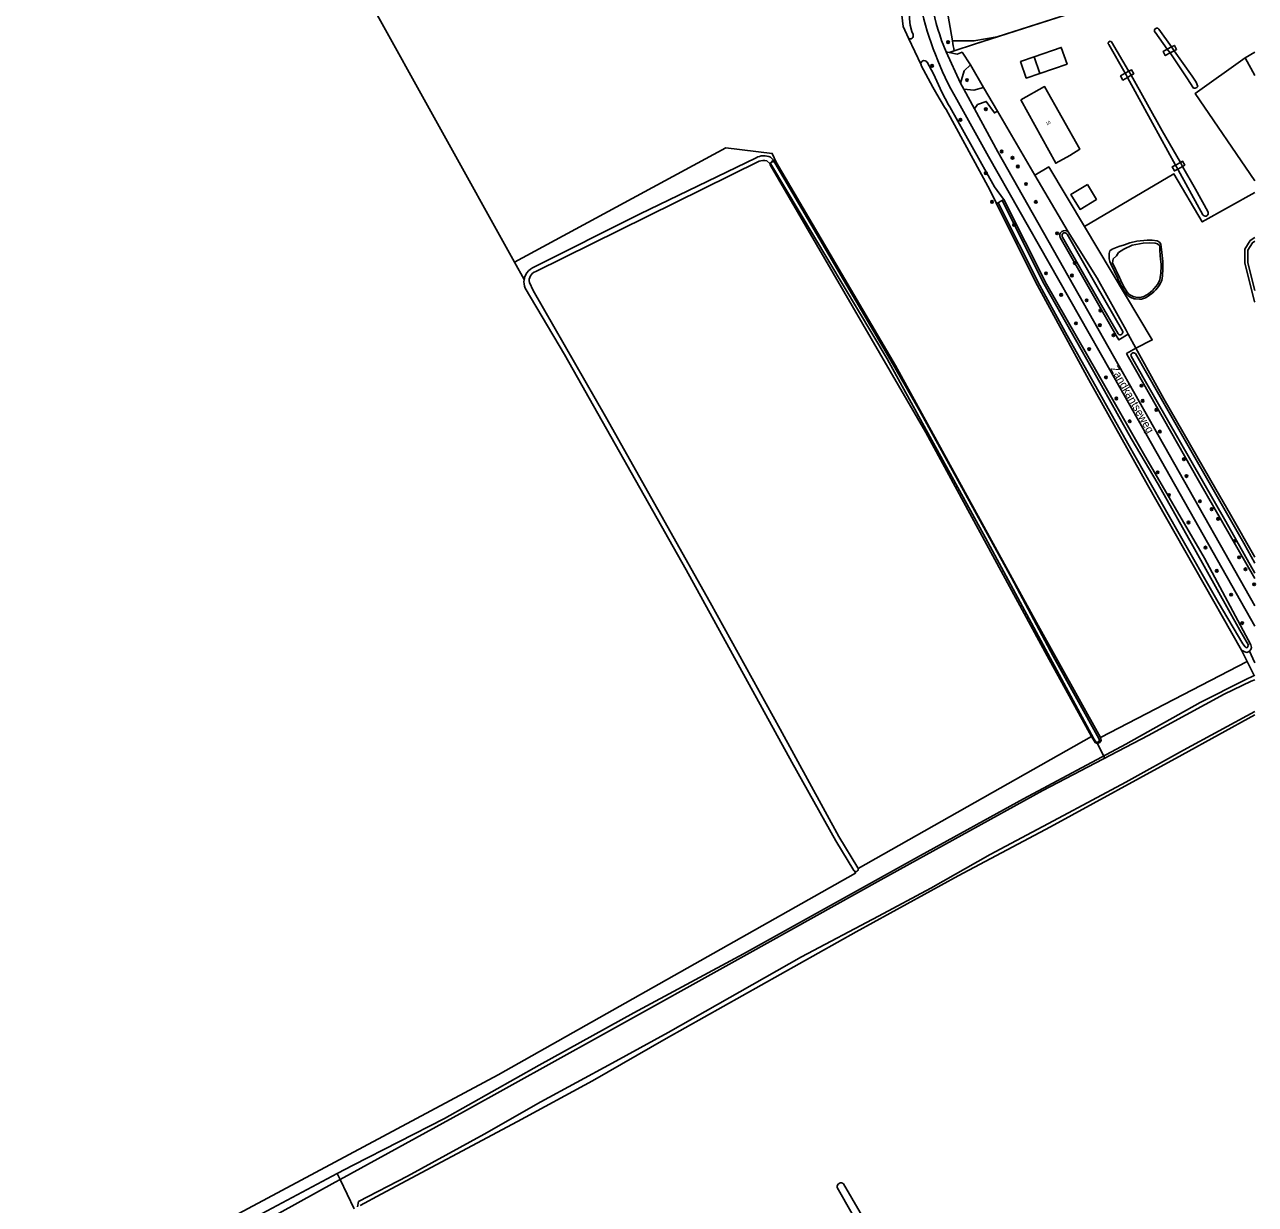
# Model space of a CAD drawing. Extents: x 137000 to 140001, y 403500 to 406000.
# Drawn here: x 139615.6 to 140000.1, y 405109.4 to 405478.2 of the extents above; entities that cross this region are included whole.
import ezdxf

# ---------------------------------------------------------------- set-up
doc = ezdxf.new("R2010")
doc.units = 0
for name, color, linetype in [('gg-afsc-draadraster', 7, 'Continuous'), ('gg-afsc-erfafscheiding', 7, 'Continuous'), ('gg-afsc-hekwerk', 7, 'Continuous'), ('gg-afsc-lijn draadraster', 7, 'Continuous'), ('gg-anno-huisnummerreeks BGT', 7, 'Continuous'), ('gg-anno-openbare ruimte label', 7, 'Continuous'), ('gg-bbg-bijgebouw', 7, 'Continuous'), ('gg-bbg-hoofdgebouw', 7, 'Continuous'), ('gg-bbg-luifel en loopbrug', 7, 'Continuous'), ('gg-knt-bronhoudergrens', 7, 'Continuous'), ('gg-knt-verharding', 7, 'Continuous'), ('gg-knt-verharding nz', 7, 'Continuous'), ('gg-kntw-bovenkant insteek waterloop', 7, 'Continuous'), ('gg-kntw-waterlijn', 7, 'Continuous'), ('gg-kwrk-duiker nz buis', 7, 'Continuous'), ('gg-kwrk-kunstwerk niveau 01', 7, 'Continuous'), ('gt-grn-groengrens', 7, 'Continuous'), ('gt-grn-vlakafsluiter', 7, 'Continuous'), ('gt-symb-boom', 7, 'Continuous')]:
    doc.layers.add(name, color=color, linetype=linetype)

# ---------------------------------------------------------------- blocks, each defined once
blk = doc.blocks.new('gt0-BOOM')
at = {"layer": 'gt-symb-boom'}
for radius in [0.4, 0.2]:
    blk.add_circle((0, 0), radius, dxfattribs=at)

msp = doc.modelspace()

# ---------------------------------------------------------------- linework, layer by layer
at = {"layer": 'gg-afsc-draadraster'}
msp.add_line((139996.89, 405467.83), (140000, 405469.63), dxfattribs=at)
msp.add_lwpolyline([(139996.89, 405467.83), (139981.26, 405456.64), (140000, 405429.35)], dxfattribs=at)
at = {"layer": 'gg-afsc-erfafscheiding'}
msp.add_line((139905.98, 405470.03), (139904.45, 405469.53), dxfattribs=at)
msp.add_lwpolyline([(139919.46, 405474.37), (139912.34, 405472.08), (139905.98, 405470.03)], dxfattribs=at)
at = {"layer": 'gg-afsc-hekwerk'}
msp.add_lwpolyline([(139949.33, 405509.28), (139949.11, 405507.9), (139952.74, 405507.73), (139952.66, 405502.48), (139962.18, 405502.59), (139962.54, 405493.26), (139961.71, 405490.23), (139960.66, 405488.19), (139958.88, 405487.07), (139912.34, 405472.08)], dxfattribs=at)
at = {"layer": 'gg-afsc-lijn draadraster'}
msp.add_line((139996.89, 405467.83), (140000, 405469.63), dxfattribs=at)
at = {"layer": 'gg-bbg-bijgebouw'}
msp.add_line((139932.81, 405462.96), (139931.02, 405468.15), dxfattribs=at)
msp.add_lwpolyline([(139932.81, 405462.96), (139941.28, 405465.86), (139939.48, 405471.07), (139931.02, 405468.15)], dxfattribs=at)
at = {"layer": 'gg-bbg-hoofdgebouw'}
msp.add_lwpolyline([(139926.82, 405454.72), (139937.73, 405434.9), (139942.11, 405437.31), (139945.26, 405439.25), (139934.27, 405458.82), (139926.82, 405454.72)], dxfattribs=at)
at = {"layer": 'gg-bbg-luifel en loopbrug'}
for points in [[(139932.81, 405462.96), (139928.56, 405461.49), (139926.77, 405466.68), (139931.02, 405468.15)], [(139947.62, 405428.26), (139942.5, 405425.14), (139945.36, 405420.45), (139950.48, 405423.56), (139947.62, 405428.26)]]:
    msp.add_lwpolyline(points, dxfattribs=at)
at = {"layer": 'gg-knt-bronhoudergrens'}
for p, q in [((139903.77, 405483.23), (139905.51, 405473.1)), ((139996.89, 405467.83), (140000, 405462.35))]:
    msp.add_line(p, q, dxfattribs=at)
for points in [[(139919.46, 405474.37), (139958.88, 405487.07), (139960.66, 405488.19), (139960.93, 405502.58), (139952.66, 405502.48), (139952.74, 405507.73), (139949.11, 405507.9), (139949.33, 405509.28)], [(139905.51, 405473.1), (139912.21, 405473.1), (139919.46, 405474.37)], [(139946.69, 405415.12), (139974.67, 405431.55), (139983.51, 405416.52), (140000, 405425.77)]]:
    msp.add_lwpolyline(points, dxfattribs=at)
msp.add_arc((139512.03, 405411.17), 398.32, 8.4971, 8.9449, dxfattribs=at)
at = {"layer": 'gg-knt-verharding'}
for p, q in [((139903.49, 405469.73), (139904.45, 405469.53)), ((139908.01, 405459.91), (139909, 405458.08)), ((139909, 405458.08), (139912.18, 405457.76)), ((139915.23, 405458.54), (139912.18, 405457.76)), ((139912.35, 405451.91), (139913.35, 405453.21))]:
    msp.add_line(p, q, dxfattribs=at)
for points in [[(139904.45, 405469.53), (139906.93, 405469.02), (139908.51, 405469.56), (139911.1, 405465.59)], [(139908.01, 405459.91), (139909.19, 405463.76), (139911.1, 405465.59)], [(139906.85, 405454.77), (139916.7, 405436.99), (139954.63, 405370.27), (140000, 405290.13)], [(139913.35, 405453.21), (139916.04, 405454.2), (139918.57, 405450.59), (139919.55, 405451.15)], [(139912.35, 405451.91), (139919.66, 405438.45), (140000, 405296.57)]]:
    msp.add_lwpolyline(points, dxfattribs=at)
for centre, radius, start, end in [((139967.89, 405497.06), 69.97, 178.4624, 202.9964), ((139996.18, 405506.02), 102.99, 192.503, 209.8436)]:
    msp.add_arc(centre, radius, start, end, dxfattribs=at)
at = {"layer": 'gg-knt-verharding nz'}
for p, q in [((139908.01, 405459.91), (139903.49, 405469.73)), ((139912.35, 405451.91), (139909, 405458.08))]:
    msp.add_line(p, q, dxfattribs=at)
at = {"layer": 'gg-kntw-bovenkant insteek waterloop'}
for p, q in [((139968.76, 405475.81), (139972.61, 405470.52)), ((139973.9, 405471.23), (139969.98, 405476.8)), ((139954.29, 405471.98), (139959.49, 405463.01)), ((139972.61, 405470.52), (139973.45, 405469.37)), ((139974.72, 405470.06), (139973.9, 405471.23)), ((139961.28, 405462.36), (139960.57, 405463.64)), ((139775.32, 405400.99), (139845.06, 405435.51)), ((139847.51, 405435.62), (139848.39, 405434.79)), ((139849.56, 405435.83), (139848.63, 405436.76)), ((139977.38, 405433.9), (139976.68, 405435.13)), ((139975.2, 405434.31), (139975.88, 405433.07)), ((139998.48, 405410.74), (140000, 405411.67)), ((139962.67, 405392.45), (139963.88, 405392.36)), ((139992.32, 405325.07), (140000, 405311.71)), ((139999.69, 405274.73), (140000, 405274.88))]:
    msp.add_line(p, q, dxfattribs=at)
for points in [[(139892.17, 405539.02), (139891.48, 405534.95), (139890.95, 405527.36), (139890.42, 405519.81), (139889.87, 405499.46), (139889.66, 405481.14), (139890.07, 405477.6), (139891.71, 405473.94)], [(139893.17, 405475.09), (139892.78, 405476.06), (139892.23, 405477.99), (139892.06, 405479.99), (139892.16, 405506.35), (139893.15, 405526.22), (139894.29, 405537.64), (139894.17, 405538.4), (139893.52, 405538.97), (139892.57, 405539.28), (139892.17, 405539.02)], [(139960.57, 405463.64), (139960.48, 405463.79), (139955.19, 405472.86)], [(139973.45, 405469.37), (139974.09, 405468.49), (139978.71, 405461.55), (139980.82, 405458.37)], [(139980.82, 405458.37), (139981.29, 405458.32), (139981.86, 405458.54), (139982.11, 405458.9), (139981.63, 405460.19), (139980.34, 405462.08), (139974.72, 405470.06)], [(139895.74, 405465.45), (139899.38, 405458.66), (139900.63, 405456.42), (139903.04, 405452.4), (139903.48, 405451.67), (139917.2, 405426.61), (139919.11, 405422.49), (139919.26, 405422.18)], [(139897.53, 405466.46), (139899.51, 405462.81), (139902.14, 405457.06), (139904.27, 405453.14), (139904.63, 405452.49), (139918.61, 405427.5), (139921.48, 405423.6), (139921.5, 405423.55)], [(139959.49, 405463.01), (139959.78, 405462.49), (139960.2, 405461.73)], [(139960.2, 405461.73), (139967.97, 405447.42), (139975.2, 405434.31)], [(139976.68, 405435.13), (139971.04, 405445.05), (139961.28, 405462.36)], [(139844.11, 405436.61), (139807.75, 405419.01), (139774.33, 405402.14)], [(139848.39, 405434.79), (139848.58, 405434.41), (139897.17, 405350.75), (139935.02, 405280.88), (139948.96, 405255.72)], [(139849.56, 405435.83), (139849.72, 405435.66), (139850.03, 405435.52), (139850.39, 405435.17)], [(139951.69, 405255.35), (139931.74, 405291.33), (139887.71, 405371.68), (139850.39, 405435.17)], [(139975.88, 405433.07), (139976.64, 405431.7), (139983.72, 405418.76), (139983.79, 405418.63)], [(139985.24, 405419.77), (139981.44, 405426.75), (139977.38, 405433.9)], [(139921.5, 405423.55), (139934.89, 405397.1), (139950.61, 405369.68), (139965.19, 405344.1), (139984.19, 405311.46), (139998.73, 405284.33), (139998.88, 405283.49), (139998.71, 405282.85), (139998.14, 405282.3), (139997.46, 405281.95), (139996.82, 405282.12), (139995.81, 405282.68)], [(139995.81, 405282.68), (139966.38, 405334.34), (139948.09, 405367.2), (139932.1, 405396.62), (139919.26, 405422.18)], [(139939.15, 405411.63), (139956.63, 405381.03), (139957.48, 405379.66), (139960.33, 405381.46)], [(139960.33, 405381.46), (139959.7, 405382.7), (139950.66, 405398.94), (139941.65, 405413.43)], [(139954.64, 405407.46), (139955.41, 405408.06), (139957.44, 405408.83), (139959.23, 405409.38), (139960.86, 405409.98), (139963.11, 405410.53), (139966.35, 405410.84), (139967.84, 405410.84), (139969.42, 405410.63), (139970.15, 405410.25), (139970.58, 405409.62), (139970.84, 405407.9)], [(139971.19, 405404.12), (139970.99, 405406.01), (139970.84, 405407.9)], [(139998.48, 405410.74), (139996.81, 405407.99), (139996.8, 405403.61), (139999.84, 405391.67), (140000, 405391.43)], [(139954.63, 405404.21), (139954.95, 405403.44), (139957.14, 405398.88)], [(139875.89, 405214.66), (139869.99, 405224.46), (139851.67, 405257.93), (139829.83, 405297.55), (139797.11, 405355.71), (139774.48, 405395.05), (139773.33, 405397.55)], [(139772.03, 405395.84), (139784.29, 405375.09), (139822.26, 405307.74), (139855.33, 405247.62), (139869.07, 405223.05), (139874.67, 405213.82)], [(139962.74, 405377.03), (139959.89, 405375.36), (139960.48, 405374.27), (139982.38, 405335.68), (140000, 405305.06)], [(139962.74, 405377.03), (139971.48, 405361.24), (139987.73, 405333.05), (139992.32, 405325.07)], [(139713.25, 405119.05), (139718.23, 405121.7), (139746.77, 405136.3), (139776.4, 405152.99), (139805.97, 405169.29), (139840.17, 405187.79), (139895.48, 405218.53), (139927.63, 405236.19), (139959.63, 405253.27), (139982.83, 405266.29), (139996.73, 405273.34), (139999.69, 405274.73)], [(139720.46, 405109.08), (139726.96, 405112.65), (139769.64, 405135.32), (139793.02, 405148.07), (139816.05, 405161.34), (139875.4, 405194.59), (139907.26, 405212.09), (139936.13, 405227.47), (139977.28, 405249.99), (140000, 405262.5)], [(139951.69, 405255.35), (139951.89, 405254.46), (139951.52, 405253.82), (139950.69, 405253.47), (139950.02, 405253.81), (139948.96, 405255.72)], [(139321.86, 405130.61), (139321.9, 405130.59), (139342.21, 405123.62), (139362.87, 405116.99), (139403.41, 405105.03), (139431.04, 405095.93), (139470.53, 405084.33), (139486.29, 405079.55), (139504.58, 405076.23), (139518.93, 405074.14), (139535.06, 405072.93), (139561.32, 405073.71), (139581.35, 405074.51), (139611.69, 405076.38), (139623.03, 405077.25), (139630.19, 405078.39), (139641.27, 405080.96), (139645.19, 405082.1), (139657.99, 405088.41), (139689.81, 405106.6), (139713.25, 405119.05)], [(139871.47, 405115.85), (139888.5, 405086.48), (139900.59, 405070.28), (139922.75, 405039.87), (139934.17, 405022.42), (139951.05, 404993.55), (139978.73, 404945.63), (139994.45, 404919.61), (140000, 404910)], [(139869.45, 405114.72), (139887, 405083.98), (139904.45, 405060.72), (139920.22, 405038.4), (139936.44, 405012.98), (139970.64, 404954.01), (139989.67, 404922.16)]]:
    msp.add_lwpolyline(points, dxfattribs=at)
for centre, radius, start, end in [((139969.35, 405476.33), 0.785, 36.6568, 221.1306), ((139892.31, 405474.69), 0.953, 231.5488, 25.1922), ((139954.77, 405472.38), 0.632, 49.3856, 220.1645), ((139896.63, 405465.96), 1.03, 29.231, 200.8802), ((139896.54, 405465.92), 0.936, 200.5815, 210.283), ((139846.53, 405432.04), 5.17, 66.0443, 117.9353), ((139846.53, 405430.14), 5.57, 79.8848, 105.2651), ((139984.5, 405419.22), 0.921, 220.2299, 36.5356), ((139940.58, 405412.28), 1.57, 47.0531, 204.4377), ((139960.42, 405405.82), 6.01, 164.1692, 195.5133), ((139945.21, 405402.62), 26.02, 350.2457, 3.3023), ((139776.74, 405397.81), 5.11, 155.6015, 172.3704), ((139775.98, 405398.22), 4.25, 112.8736, 156.4334), ((139776.12, 405398.23), 2.88, 106.2258, 193.641), ((139776.73, 405397.81), 5.11, 172.415, 202.7913), ((139980.76, 405408.44), 25.48, 202.0301, 213.9325), ((139960.87, 405402.56), 10.89, 300.0032, 336.4588), ((139963.31, 405397.08), 4.67, 217.7841, 262.1661), ((139963.88, 405396.59), 4.23, 269.8733, 305.1442), ((139875.32, 405214.21), 0.758, 211.1163, 236.446), ((139875.31, 405214.2), 0.747, 236.6567, 17.5718), ((139875.32, 405214.21), 0.73, 17.2651, 38.5294), ((139870.65, 405114.95), 1.22, 47.5261, 190.8625)]:
    msp.add_arc(centre, radius, start, end, dxfattribs=at)
at = {"layer": 'gg-kntw-waterlijn'}
for p, q in [((139921.5, 405423.55), (139921.05, 405423.28)), ((139919.81, 405422.52), (139919.26, 405422.18)), ((139962.75, 405393.04), (139963.88, 405392.96))]:
    msp.add_line(p, q, dxfattribs=at)
for points in [[(139849.56, 405435.83), (139849.07, 405435.39), (139848.39, 405434.79)], [(139885.07, 405373.76), (139915.79, 405317.82), (139949.61, 405254.95), (139950.32, 405254.02), (139950.8, 405253.85), (139951.4, 405254.38), (139951.26, 405255.11), (139936.98, 405280.8), (139923.93, 405305.27), (139895.2, 405357.56), (139885.54, 405374.45), (139849.96, 405435.03), (139849.65, 405435.33), (139849.19, 405435.32), (139848.64, 405434.8), (139885.07, 405373.76)], [(139919.81, 405422.52), (139932.78, 405396.66), (139940.84, 405381.99), (139960.27, 405347.3), (139975.9, 405319.73), (139988.48, 405297.65), (139996.17, 405284.68), (139996.91, 405283.73), (139997.27, 405283.43), (139997.6, 405283.56), (139997.9, 405283.98), (139997.92, 405284.26), (139995.29, 405288.91), (139981.06, 405314.4), (139969.74, 405334.52), (139961.28, 405348.83), (139950.57, 405368.02), (139934.5, 405396.37), (139934.18, 405397.08), (139921.05, 405423.28)], [(139939.85, 405411.82), (139951.34, 405391.81), (139957.26, 405381.51)], [(139941.27, 405412.71), (139950.27, 405397.01), (139958.66, 405382.32)], [(139957.68, 405399.12), (139955.49, 405403.7), (139955.58, 405404.36), (139955.74, 405404.96), (139956.69, 405405.9), (139957.36, 405406.93), (139958.98, 405408), (139961.63, 405409.3), (139965.07, 405409.86), (139967.16, 405409.98), (139968.79, 405409.86), (139969.58, 405409.66), (139970.24, 405409.03)], [(139970.6, 405404.05), (139970.4, 405405.95), (139970.24, 405407.86)], [(140000, 405395.1), (139997.8, 405403.74), (139997.81, 405407.71), (139999.21, 405410.01), (140000, 405410.5)], [(139961.27, 405374.54), (139965.37, 405367.41), (139990.87, 405322.87), (140000, 405306.7)], [(139962.62, 405375.4), (139969.95, 405362.56), (139996.48, 405316.16), (140000, 405309.86)], [(139714.15, 405117.2), (139752.77, 405138.38), (139795.51, 405162.12), (139841.2, 405187.59), (139883.15, 405210.91), (139933.76, 405238.79), (139966.62, 405256.02), (139990.4, 405268.95), (139998.81, 405272.98), (140000, 405273.41)], [(139719.64, 405108.64), (139719.88, 405110.33), (139735.27, 405118.26), (139759.13, 405131.34), (139776.93, 405141.49), (139799.18, 405153.57), (139816.65, 405163.15), (139858.28, 405186.77), (139882.37, 405199.48), (139898.68, 405208.32), (139917.24, 405218.84), (139938.62, 405230.16), (139959.66, 405241.4), (139977.62, 405251.4), (140000, 405263.48)], [(139321.3, 405128.59), (139353.84, 405117.82), (139377.3, 405110.72), (139422.14, 405096.54), (139442.29, 405090.31), (139466.56, 405083.22), (139488.65, 405076.93), (139508.21, 405073.15), (139527.27, 405070.94), (139553.54, 405070.96), (139597.72, 405073.56), (139633.61, 405076.45), (139640.23, 405077.65), (139643.83, 405078.55), (139646.18, 405079.24), (139648.76, 405080.32), (139672.72, 405094.25), (139712.6, 405116.35), (139714.15, 405117.2)]]:
    msp.add_lwpolyline(points, dxfattribs=at)
for centre, radius, start, end in [((139940.55, 405412.28), 0.84, 31.0045, 213.3463), ((139964.71, 405408.4), 5.56, 354.4253, 6.55), ((139946.03, 405402.51), 24.62, 350.5161, 3.5969), ((139980.49, 405408.29), 24.58, 201.8921, 213.8909), ((139960.87, 405402.56), 10.3, 299.8497, 336.4564), ((139963.31, 405397.08), 4.08, 217.7787, 262.1638), ((139963.89, 405396.58), 3.62, 269.8254, 305.6287), ((139957.88, 405382.06), 0.827, 222.2115, 17.7352), ((139962.07, 405374.77), 0.833, 48.8607, 196.2136)]:
    msp.add_arc(centre, radius, start, end, dxfattribs=at)
at = {"layer": 'gg-kwrk-duiker nz buis'}
for p, q in [((139998.17, 405282.59), (140000, 405278.69)), ((139950.68, 405253.66), (139952.94, 405248.98))]:
    msp.add_line(p, q, dxfattribs=at)
at = {"layer": 'gg-kwrk-kunstwerk niveau 01'}
for p, q in [((139973.9, 405471.23), (139972.61, 405470.52)), ((139974.72, 405470.06), (139973.45, 405469.37)), ((139959.49, 405463.01), (139960.57, 405463.64)), ((139960.2, 405461.73), (139961.28, 405462.36)), ((139975.2, 405434.31), (139976.68, 405435.13)), ((139975.88, 405433.07), (139977.38, 405433.9))]:
    msp.add_line(p, q, dxfattribs=at)
for points in [[(139972.61, 405470.52), (139971.26, 405469.79), (139971.94, 405468.54), (139973.45, 405469.37)], [(139974.72, 405470.06), (139975.49, 405470.48), (139974.81, 405471.72), (139973.9, 405471.23)], [(139959.49, 405463.01), (139958.03, 405462.15), (139958.76, 405460.89), (139960.2, 405461.73)], [(139961.28, 405462.36), (139962.14, 405462.86), (139961.4, 405464.12), (139960.57, 405463.64)], [(139977.38, 405433.9), (139978.06, 405434.28), (139977.37, 405435.52), (139976.68, 405435.13)], [(139975.2, 405434.31), (139974.12, 405433.71), (139974.81, 405432.47), (139975.88, 405433.07)]]:
    msp.add_lwpolyline(points, dxfattribs=at)
at = {"layer": 'gt-grn-groengrens'}
for p, q in [((139696.99, 405533.17), (139768.62, 405403.95)), ((139891.71, 405473.94), (139895.67, 405465.59)), ((139915.23, 405458.54), (139911.1, 405465.59)), ((139931.25, 405431.18), (139919.55, 405451.15)), ((139941.65, 405413.43), (139931.25, 405431.18)), ((139771.67, 405398.49), (139768.62, 405403.95)), ((139960.33, 405381.46), (139962.74, 405377.03)), ((139995.81, 405282.68), (139997.55, 405279.11)), ((139997.55, 405279.11), (139951.69, 405255.35)), ((139997.55, 405279.11), (139999.69, 405274.73)), ((139876.02, 405214.42), (139948.96, 405255.72))]:
    msp.add_line(p, q, dxfattribs=at)
for points in [[(139850.39, 405435.17), (139849.2, 405437.96), (139834.68, 405439.72), (139768.62, 405403.95)], [(139946.69, 405415.12), (139935.54, 405433.75), (139931.25, 405431.18)], [(139946.69, 405415.12), (139967.92, 405379.67), (139962.74, 405377.03)], [(139874.9, 405213.58), (139875.24, 405212.97), (139763.52, 405149.97), (139670.49, 405100.12), (139641.07, 405084.25), (139629.74, 405082.45), (139593.86, 405079.28), (139546.35, 405076.74), (139544.18, 405080.12)]]:
    msp.add_lwpolyline(points, dxfattribs=at)
at = {"layer": 'gt-grn-vlakafsluiter'}
for p, q in [((139919.55, 405451.15), (139915.23, 405458.54)), ((139713.25, 405119.05), (139714.15, 405117.2)), ((139718.61, 405108.07), (139714.15, 405117.2))]:
    msp.add_line(p, q, dxfattribs=at)
msp.add_lwpolyline([(139921.05, 405423.28), (139920.43, 405422.9), (139919.81, 405422.52)], dxfattribs=at)

# ---------------------------------------------------------------- block references
at = {"layer": 'gt-symb-boom'}
for p in [(139904.11, 405472.71), (139899.11, 405465.34), (139910.02, 405460.88), (139915.93, 405451.76), (139907.97, 405448.45), (139920.85, 405438.54), (139924.26, 405436.59), (139915.9, 405431.77), (139925.91, 405433.84), (139928.46, 405428.39), (139917.85, 405422.81), (139931.51, 405422.79), (139924.75, 405415.64), (139938.19, 405412.96), (139943.68, 405403.67), (139934.71, 405400.46), (139942.81, 405399.77), (139939.44, 405393.73), (139947.4, 405392.02), (139951.71, 405388.84), (139944.06, 405384.84), (139951.52, 405384.28), (139955.77, 405381.11), (139948.19, 405376.79), (139953.43, 405367.93), (139964.54, 405365.36), (139956.69, 405361.32), (139964.91, 405360.61), (139969.17, 405357.78), (139960.87, 405354.23), (139970.29, 405351), (139977.79, 405342.36), (139969.58, 405338.26), (139978.58, 405337.1), (139973.14, 405331.16), (139982.79, 405329.22), (139986.45, 405326.73), (139988.47, 405323.72), (139979.22, 405322.57), (139993.62, 405316.78), (139984.55, 405314.74), (139995.05, 405311.7), (139988.05, 405307.49), (139997.04, 405307.97), (139992.56, 405300.03), (139999.72, 405303.24), (139996.02, 405291.15)]:
    msp.add_blockref('gt0-BOOM', p, dxfattribs=at)

# ---------------------------------------------------------------- texts
at = {"layer": 'gg-anno-huisnummerreeks BGT'}
msp.add_text('10', height=1, rotation=28.8, dxfattribs=at).set_placement((139934.93, 405446.67))
at = {"layer": 'gg-anno-openbare ruimte label'}
msp.add_text('Zandkantseweg', height=2.5, rotation=299.7, dxfattribs=at).set_placement((139954.76, 405370.7))

doc.saveas('drawing.dxf')
